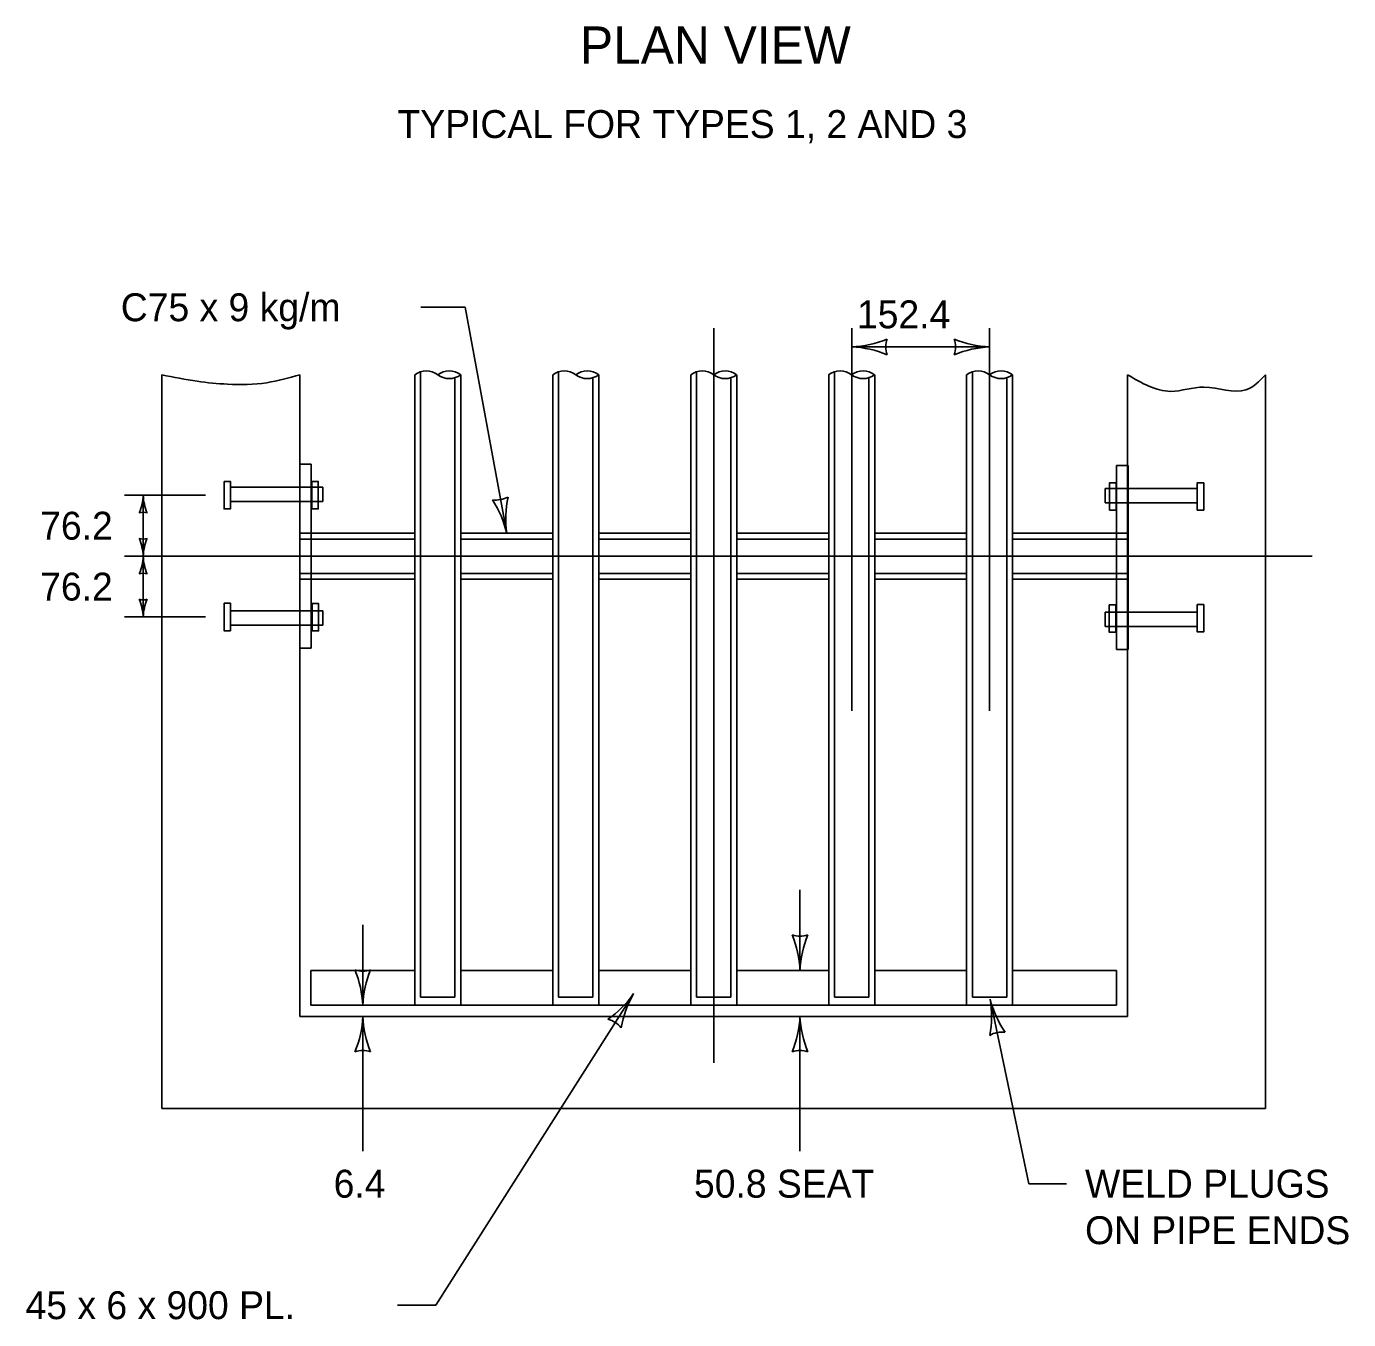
# Model space of a CAD drawing. Extents: x 49991.4 to 50021, y 49987.6 to 50011.4.
# Drawn here: x 50008.628 to 50011.473, y 49992.879 to 49995.661 of the extents above; entities that cross this region are included whole.
import ezdxf

# ---------------------------------------------------------------- set-up
doc = ezdxf.new("R2010")
doc.units = 0
for name, color, linetype in [('Level 1', 7, 'Continuous'), ('Level 2', 7, 'Continuous'), ('Level 3', 7, 'Continuous'), ('Level 4', 7, 'Continuous'), ('Level 5', 7, 'Continuous')]:
    doc.layers.add(name, color=color, linetype=linetype)

msp = doc.modelspace()

# ---------------------------------------------------------------- linework, layer by layer
at = {"layer": 'Level 1'}
for p, q in [((50008.919, 49993.3336), (50008.919, 49994.9114)), ((50009.2159, 49993.5315), (50009.2159, 49994.9114)), ((50009.4632, 49994.9114), (50009.4632, 49994.4719)), ((50009.5622, 49994.9114), (50009.5622, 49993.5553)), ((50009.7602, 49994.9114), (50009.7602, 49993.5553)), ((50009.8591, 49994.9114), (50009.8591, 49993.5553)), ((50010.0571, 49994.9114), (50010.0571, 49993.5553)), ((50010.156, 49994.9114), (50010.156, 49993.5553)), ((50010.3539, 49994.9114), (50010.3539, 49994.4656)), ((50010.4529, 49994.9114), (50010.4529, 49993.5553)), ((50010.6507, 49994.9114), (50010.6507, 49993.5553)), ((50010.7497, 49994.9114), (50010.7497, 49993.5553)), ((50010.9971, 49993.5315), (50010.9971, 49994.9114)), ((50011.2939, 49993.3336), (50011.2939, 49994.9114)), ((50009.2159, 49994.5211), (50009.2159, 49994.719)), ((50009.2407, 49994.719), (50009.2159, 49994.719)), ((50009.2407, 49994.5211), (50009.2407, 49994.719)), ((50010.9734, 49994.5185), (50010.9734, 49994.7164)), ((50010.9981, 49994.7164), (50010.9734, 49994.7164)), ((50010.9981, 49994.5185), (50010.9981, 49994.7164)), ((50009.2557, 49994.6695), (50009.2654, 49994.6695)), ((50009.2654, 49994.6695), (50009.2654, 49994.6387)), ((50010.9487, 49994.6669), (50010.9487, 49994.6359)), ((50010.9487, 49994.6669), (50010.9584, 49994.6669)), ((50009.2557, 49994.6387), (50009.2654, 49994.6387)), ((50010.9584, 49994.6359), (50010.9487, 49994.6359)), ((50009.2159, 49994.5706), (50009.4632, 49994.5706)), ((50009.5622, 49994.5706), (50009.7602, 49994.5706)), ((50009.8596, 49994.5706), (50010.0571, 49994.5706)), ((50010.156, 49994.5706), (50010.3539, 49994.5706)), ((50010.4529, 49994.5706), (50010.6507, 49994.5706)), ((50010.7497, 49994.5706), (50010.9971, 49994.5706)), ((50009.2159, 49994.3232), (50009.2159, 49994.5211)), ((50009.2407, 49994.3232), (50009.2407, 49994.5211)), ((50010.9734, 49994.3206), (50010.9734, 49994.5185)), ((50010.9981, 49994.3206), (50010.9981, 49994.5185)), ((50009.2159, 49994.4716), (50009.4632, 49994.4716)), ((50009.4632, 49994.4716), (50009.4632, 49993.5553)), ((50009.5622, 49994.4716), (50009.7602, 49994.4716)), ((50009.8591, 49994.4716), (50010.0571, 49994.4716)), ((50010.156, 49994.4716), (50010.3539, 49994.4716)), ((50010.3539, 49994.4716), (50010.3539, 49993.5553)), ((50010.4529, 49994.4716), (50010.6507, 49994.4716)), ((50010.7497, 49994.4716), (50010.9971, 49994.4716)), ((50009.2563, 49994.4037), (50009.2654, 49994.4037)), ((50009.2654, 49994.4037), (50009.2654, 49994.3727)), ((50010.9487, 49994.4009), (50010.9487, 49994.37)), ((50010.9487, 49994.4009), (50010.9576, 49994.4009)), ((50009.2563, 49994.3727), (50009.2654, 49994.3727)), ((50010.9487, 49994.37), (50010.9576, 49994.37)), ((50009.2407, 49994.3232), (50009.2159, 49994.3232)), ((50010.9981, 49994.3206), (50010.9734, 49994.3206)), ((50009.2397, 49993.6305), (50009.4632, 49993.6305)), ((50009.2397, 49993.6305), (50009.2397, 49993.5553)), ((50009.5622, 49993.6305), (50009.7602, 49993.6305)), ((50009.8591, 49993.6305), (50010.0571, 49993.6305)), ((50010.156, 49993.6305), (50010.3539, 49993.6305)), ((50010.4529, 49993.6305), (50010.6507, 49993.6305)), ((50010.7497, 49993.6305), (50010.9734, 49993.6305)), ((50010.9734, 49993.6305), (50010.9734, 49993.5553)), ((50009.2397, 49993.5553), (50010.9734, 49993.5553)), ((50009.2159, 49993.5315), (50010.9971, 49993.5315)), ((50008.919, 49993.3336), (50011.2939, 49993.3336))]:
    msp.add_line(p, q, dxfattribs=at)
for points in [[(50009.2416, 49994.6819), (50009.2416, 49994.623), (50009.2557, 49994.623), (50009.2557, 49994.6819)], [(50010.9723, 49994.6791), (50010.9723, 49994.6203), (50010.9584, 49994.6203), (50010.9584, 49994.6791)], [(50009.2423, 49994.4192), (50009.2423, 49994.3605), (50009.2563, 49994.3605), (50009.2563, 49994.4192)], [(50010.9717, 49994.4165), (50010.9717, 49994.3577), (50010.9576, 49994.3577), (50010.9576, 49994.4165)]]:
    msp.add_lwpolyline(points, close=True, dxfattribs=at)
for centre, major_axis, start_param, end_param in [((50009.488, 49994.8789), (0, 0.0408), 5.632065, 6.934304), ((50009.5375, 49994.8789), (0, 0.0408), 5.632065, 6.934304), ((50009.7849, 49994.8789), (0, 0.0408), 5.632065, 6.934304), ((50009.8344, 49994.8789), (0, 0.0408), 5.632065, 6.934304), ((50010.0818, 49994.8789), (0, 0.0408), 5.632065, 6.934304), ((50010.1312, 49994.8789), (0, 0.0408), 5.632065, 6.934304), ((50010.3786, 49994.8789), (0, 0.0408), 5.632065, 6.934304), ((50010.4281, 49994.8789), (0, 0.0408), 5.632065, 6.934304), ((50010.6755, 49994.8789), (0, 0.0408), 5.632065, 6.934304), ((50010.725, 49994.8789), (0, 0.0408), 5.632065, 6.934304), ((50009.5375, 49994.9439), (0, -0.0408), 5.632066, 6.934305), ((50009.8344, 49994.9439), (0, -0.0408), 5.632066, 6.934305), ((50010.1312, 49994.9439), (0, -0.0408), 5.632066, 6.934305), ((50010.4281, 49994.9439), (0, -0.0408), 5.632066, 6.934305), ((50010.725, 49994.9439), (0, -0.0408), 5.632066, 6.934305)]:
    msp.add_ellipse(centre, major_axis=major_axis, ratio=0.99996, start_param=start_param, end_param=end_param, dxfattribs=at)
for points in [[(50008.919, 49994.9114), (50008.9952, 49994.8974), (50009.0606, 49994.8912), (50009.1448, 49994.8944), (50009.2159, 49994.9114)], [(50010.9971, 49994.9114), (50011.0898, 49994.8757), (50011.1614, 49994.885), (50011.2518, 49994.8789), (50011.2939, 49994.9114)]]:
    msp.add_spline(points, degree=3, dxfattribs=at)
at = {"layer": 'Level 3'}
for p, q in [((50009.4762, 49995.0566), (50009.5715, 49995.0566)), ((50009.5715, 49995.0566), (50009.6612, 49994.5706)), ((50010.4034, 49994.9714), (50010.7002, 49994.9714)), ((50009.0129, 49994.6524), (50008.839, 49994.6524)), ((50008.879, 49994.6524), (50008.879, 49994.5212)), ((50008.879, 49994.5212), (50008.879, 49994.3905)), ((50009.0129, 49994.3905), (50008.839, 49994.3905)), ((50010.2922, 49993.6305), (50010.2922, 49993.8039)), ((50009.3515, 49993.5553), (50009.3515, 49993.7287)), ((50009.5084, 49992.9103), (50009.9341, 49993.5803)), ((50010.7849, 49993.1716), (50010.7012, 49993.5686)), ((50010.2922, 49993.5315), (50010.2922, 49993.2416)), ((50009.3515, 49993.5107), (50009.3515, 49993.2416)), ((50010.8655, 49993.1716), (50010.7849, 49993.1716)), ((50009.4262, 49992.9103), (50009.5084, 49992.9103))]:
    msp.add_line(p, q, dxfattribs=at)
for centre, radius, start, end in [((50010.3919, 49995.2041), 0.233, 272.8273, 292.0772), ((50010.5316, 49994.9714), 0.0548, 162.1388, 197.8612), ((50010.7094, 49995.1935), 0.2223, 247.456, 267.6395), ((50010.572, 49994.9714), 0.0548, 342.1388, 17.8612), ((50010.3942, 49994.7493), 0.2223, 67.456, 87.6395), ((50010.7117, 49994.7387), 0.233, 92.8273, 112.0772), ((50008.7679, 49994.657), 0.1112, 337.456, 357.6395), ((50008.9954, 49994.6581), 0.1165, 182.8273, 202.0772), ((50009.6379, 49994.6967), 0.0548, 262.5961, 298.3185), ((50009.4344, 49994.5171), 0.233, 13.2846, 32.5344), ((50009.8813, 49994.6019), 0.2223, 167.9133, 188.0968), ((50008.879, 49994.5883), 0.0274, 72.1388, 107.8612), ((50008.879, 49994.5853), 0.0274, 252.1388, 287.8612), ((50008.7626, 49994.5155), 0.1165, 2.8273, 22.0772), ((50008.9901, 49994.5166), 0.1112, 157.456, 177.6395), ((50008.7679, 49994.5258), 0.1112, 337.456, 357.6395), ((50008.9954, 49994.5269), 0.1165, 182.8273, 202.0772), ((50008.879, 49994.4571), 0.0274, 72.1388, 107.8612), ((50008.879, 49994.4546), 0.0274, 252.1388, 287.8612), ((50008.7626, 49994.3848), 0.1165, 2.8273, 22.0772), ((50008.9901, 49994.3859), 0.1112, 157.456, 177.6395), ((50009.7515, 49993.7072), 0.2223, 305.0252, 325.2087), ((50010.1367, 49993.4652), 0.233, 150.3965, 169.6464), ((50010.482, 49993.5317), 0.2223, 349.3614, 9.5449), ((50010.9265, 49993.6279), 0.233, 194.7327, 213.9825), ((50009.8653, 49993.4721), 0.0548, 39.708, 75.4304), ((50010.7276, 49993.4431), 0.0548, 84.0442, 119.7666)]:
    msp.add_arc(centre, radius, start, end, dxfattribs=at)
for centre, major_axis, start_param, end_param in [((50010.2922, 49993.7587), (0, -0.0548), 5.971449, 6.594922), ((50010.0595, 49993.619), (0, 0.233), 4.761735, 5.097708), ((50010.5143, 49993.6213), (0, 0.2223), 1.177329, 1.529598), ((50009.3515, 49993.6835), (0, -0.0548), 5.971449, 6.594922), ((50009.1188, 49993.5438), (0, 0.233), 4.761735, 5.097708), ((50009.5736, 49993.5461), (0, 0.2223), 1.177329, 1.529598), ((50009.1294, 49993.5407), (0, -0.2223), 1.177329, 1.529598), ((50009.5842, 49993.543), (0, -0.233), 4.761735, 5.097708), ((50010.0701, 49993.5407), (0, -0.2223), 1.177329, 1.529598), ((50010.5249, 49993.543), (0, -0.233), 4.761735, 5.097708), ((50009.3515, 49993.4033), (0, 0.0548), 5.971449, 6.594922), ((50010.2922, 49993.4033), (0, 0.0548), 5.971449, 6.594922)]:
    msp.add_ellipse(centre, major_axis=major_axis, ratio=0.99996, start_param=start_param, end_param=end_param, dxfattribs=at)
at = {"layer": 'Level 4'}
for p, q in [((50009.4757, 49994.9179), (50009.4757, 49993.5731)), ((50009.7726, 49994.9179), (50009.7726, 49993.5731)), ((50010.0694, 49994.9179), (50010.0694, 49993.5731)), ((50010.3663, 49994.9179), (50010.3663, 49993.5731)), ((50010.6631, 49994.9179), (50010.6631, 49993.5731)), ((50009.5498, 49994.9049), (50009.5498, 49993.5731)), ((50009.8467, 49994.9049), (50009.8467, 49993.5731)), ((50010.1436, 49994.9049), (50010.1436, 49993.5731)), ((50010.4405, 49994.9049), (50010.4405, 49993.5731)), ((50010.7373, 49994.9049), (50010.7373, 49993.5731)), ((50009.2557, 49994.6695), (50009.0674, 49994.6695)), ((50010.9584, 49994.6669), (50011.1465, 49994.6669)), ((50009.2557, 49994.6387), (50009.0674, 49994.6387)), ((50010.9584, 49994.6359), (50011.1465, 49994.6359)), ((50009.2159, 49994.5581), (50009.4632, 49994.5581)), ((50009.5622, 49994.5581), (50009.7602, 49994.5581)), ((50009.8596, 49994.5581), (50010.0571, 49994.5581)), ((50010.156, 49994.5581), (50010.3539, 49994.5581)), ((50010.4529, 49994.5581), (50010.6507, 49994.5581)), ((50010.7497, 49994.5581), (50010.9971, 49994.5581)), ((50009.2159, 49994.4841), (50009.4632, 49994.4841)), ((50009.5622, 49994.4841), (50009.7602, 49994.4841)), ((50009.8591, 49994.4841), (50010.0571, 49994.4841)), ((50010.156, 49994.4841), (50010.3539, 49994.4841)), ((50010.4529, 49994.4841), (50010.6507, 49994.4841)), ((50010.7497, 49994.4841), (50010.9971, 49994.4841)), ((50009.2563, 49994.4037), (50009.0674, 49994.4037)), ((50010.9576, 49994.4009), (50011.1465, 49994.4009)), ((50009.2563, 49994.3727), (50009.0674, 49994.3727)), ((50010.9576, 49994.37), (50011.1465, 49994.37)), ((50009.4757, 49993.5731), (50009.5498, 49993.5731)), ((50009.7726, 49993.5731), (50009.8467, 49993.5731)), ((50010.0694, 49993.5731), (50010.1436, 49993.5731)), ((50010.3663, 49993.5731), (50010.4405, 49993.5731)), ((50010.6631, 49993.5731), (50010.7373, 49993.5731))]:
    msp.add_line(p, q, dxfattribs=at)
for points in [[(50009.0529, 49994.6819), (50009.0529, 49994.623), (50009.0668, 49994.623), (50009.0668, 49994.6819)], [(50011.161, 49994.6791), (50011.161, 49994.6203), (50011.147, 49994.6203), (50011.147, 49994.6791)], [(50009.0529, 49994.4199), (50009.0529, 49994.361), (50009.0668, 49994.361), (50009.0668, 49994.4199)], [(50011.161, 49994.4172), (50011.161, 49994.3584), (50011.147, 49994.3584), (50011.147, 49994.4172)]]:
    msp.add_lwpolyline(points, close=True, dxfattribs=at)
at = {"layer": 'Level 5'}
for p, q in [((50010.1065, 49995.0114), (50010.1065, 49993.4315)), ((50010.4034, 49994.1888), (50010.4034, 49995.0114)), ((50010.7002, 49994.1888), (50010.7002, 49995.0114)), ((50011.3939, 49994.5212), (50008.839, 49994.5212))]:
    msp.add_line(p, q, dxfattribs=at)

# ---------------------------------------------------------------- texts
at = {"layer": 'Level 2'}
for s, height, p in [('PLAN VIEW', 0.08, (50009.8188, 49995.5806)), ('TYPICAL FOR TYPES 1, 2 AND 3', 0.06, (50009.4262, 49995.4206)), ('C75 x 9 kg/m', 0.06, (50008.8308, 49995.0266)), ('152.4', 0.06, (50010.4148, 49995.0114)), ('76.2', 0.06, (50008.6573, 49994.5568)), ('76.2', 0.06, (50008.6573, 49994.4258)), ('6.4', 0.06, (50009.2888, 49993.1416)), ('50.8 SEAT', 0.06, (50010.0641, 49993.1416)), ('WELD PLUGS ', 0.06, (50010.9055, 49993.1416)), ('ON PIPE ENDS', 0.06, (50010.9055, 49993.0416)), ('45 x 6 x 900 PL.', 0.06, (50008.6259, 49992.8803))]:
    msp.add_text(s, height=height, dxfattribs=at).set_placement(p)

doc.saveas('drawing.dxf')
